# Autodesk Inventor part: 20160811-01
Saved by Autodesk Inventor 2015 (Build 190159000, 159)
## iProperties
Created: 2016-08
Part Number: 20160811-01
Material: Ocel
Document SubType Name: Modeling
Designer: navara
Density: 7.85 g/cm^3
Appearance: Plech
Author: navara
Beppe: 20160811-01.ipt
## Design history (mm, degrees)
feature "Base1"
node "Těleso1"
